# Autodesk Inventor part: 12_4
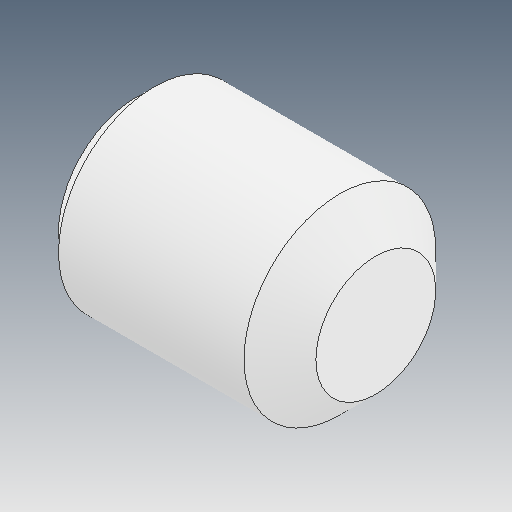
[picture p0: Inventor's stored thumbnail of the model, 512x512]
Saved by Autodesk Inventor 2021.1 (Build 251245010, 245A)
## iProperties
Created: 2021-06
Part Number: 12_4
Material: Ogólny
Document SubType Name: Modeling
Designer: user
Density: 1 g/cm^3
Appearance: Domyślna
Author: user
Revision Number: ÈÎºÎ
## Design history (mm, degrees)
feature "ÊäÈë1"
node "Bryła1"
